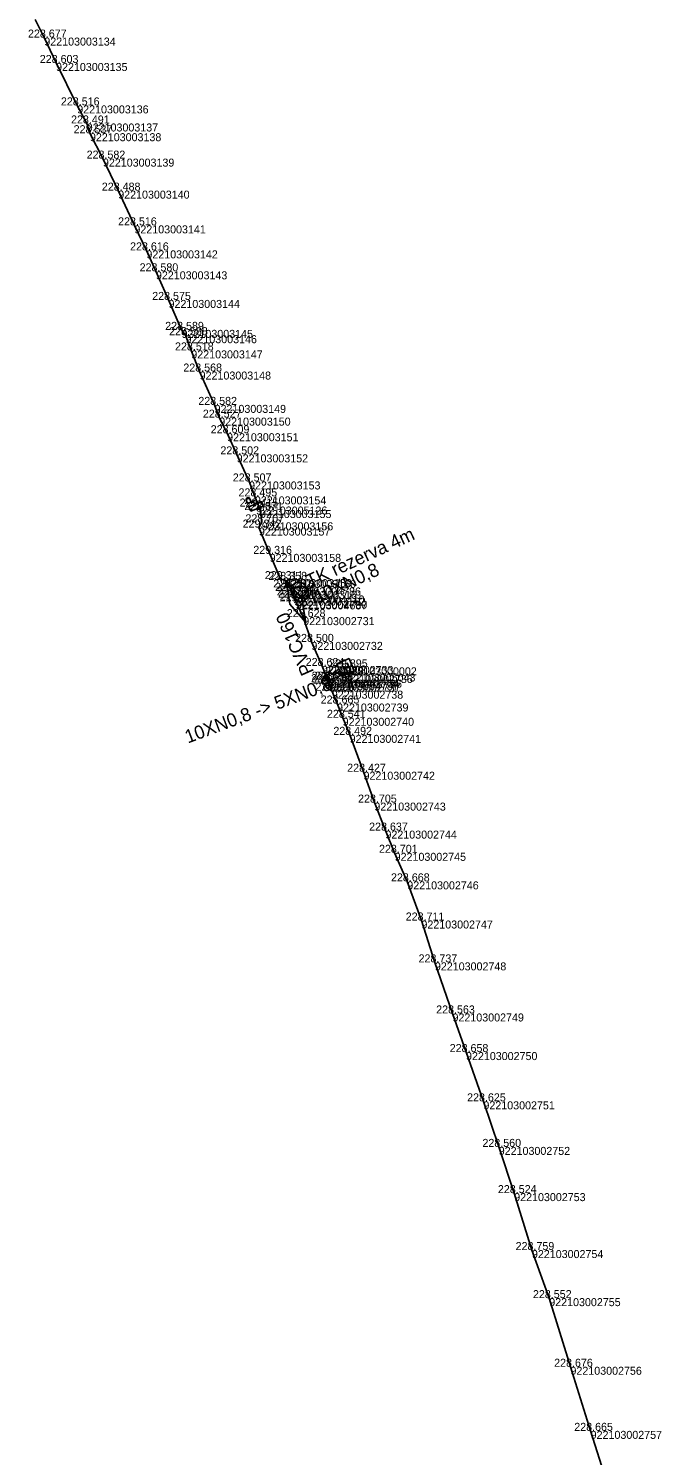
# Model space of a CAD drawing. Extents: x -771047 to -756200, y -1053876 to -1046520.
# Drawn here: x -769185.7 to -769090.7, y -1051176.3 to -1050962.3 of the extents above; entities that cross this region are included whole.
import ezdxf

# ---------------------------------------------------------------- set-up
doc = ezdxf.new("R2010")
doc.units = 0
for name, color, linetype in [('Vrstva 32', 7, 'Continuous'), ('Vrstva 33', 7, 'Continuous'), ('Vrstva 60', 7, 'Continuous'), ('Vrstva 61', 7, 'Continuous')]:
    doc.layers.add(name, color=color, linetype=linetype)

msp = doc.modelspace()

# ---------------------------------------------------------------- linework, layer by layer
at = {"layer": 'Vrstva 32'}
for p, q in [((-769141.25, -1051059.5), (-769141.73, -1051060.08)), ((-769141.73, -1051060.08), (-769140.81, -1051061.33)), ((-769141.69, -1051060.13), (-769140.21, -1051059.99)), ((-769141.42, -1051059.7), (-769140.92, -1051059.65)), ((-769141.41, -1051060.51), (-769140.02, -1051060.37)), ((-769139.85, -1051060.16), (-769141.25, -1051059.5)), ((-769141.14, -1051060.88), (-769140.38, -1051060.81)), ((-769140.81, -1051061.33), (-769139.85, -1051060.16)), ((-769140.86, -1051061.26), (-769140.75, -1051061.25))]:
    msp.add_line(p, q, dxfattribs=at)
for points in [[(-769184.68, -1050960.95), (-769183.32, -1050963.66), (-769181.55, -1050967.47), (-769178.38, -1050973.83), (-769176.95, -1050976.54), (-769176.47, -1050978), (-769174.52, -1050981.81), (-769172.23, -1050986.61), (-769169.8, -1050991.82), (-769168, -1050995.57), (-769166.57, -1050998.71), (-769164.68, -1051003), (-769162.72, -1051007.49), (-769162.13, -1051008.29), (-769161.26, -1051010.57), (-769160.01, -1051013.74), (-769157.76, -1051018.74), (-769157.07, -1051020.65), (-769155.89, -1051022.99), (-769154.45, -1051026.16), (-769152.59, -1051030.22), (-769151.72, -1051032.46), (-769150.95, -1051034.51), (-769150.68, -1051036.35), (-769151.11, -1051037.14), (-769149.5, -1051041.08), (-769147.88, -1051044.87), (-769147.24, -1051044.98), (-769146.52, -1051046.12), (-769146.24, -1051046.63), (-769145.98, -1051047.32), (-769145.81, -1051047.64)], [(-769147.03, -1051045.04), (-769144.66, -1051047.79), (-769144.1, -1051051.39), (-769146.47, -1051048.63), (-769147.03, -1051045.04)], [(-769145.81, -1051047.64), (-769145.58, -1051048.1), (-769145.57, -1051048.21), (-769144.47, -1051050.57), (-769143.24, -1051054.28), (-769141.65, -1051057.9), (-769140.76, -1051059.95), (-769140.85, -1051060.32), (-769140.58, -1051060.54)], [(-769140.36, -1051059.95), (-769138.75, -1051059.25), (-769138.35, -1051059.02), (-769138.14, -1051058.1)], [(-769140.76, -1051059.95), (-769140.36, -1051059.95), (-769140.58, -1051060.54)], [(-769140.76, -1051059.95), (-769140.36, -1051059.95), (-769140.58, -1051060.54), (-769140.18, -1051061.6)], [(-769098.99, -1051179.97), (-769101.34, -1051172.59), (-769104.37, -1051162.98), (-769107.55, -1051152.69), (-769110.15, -1051145.48), (-769112.81, -1051136.94), (-769115.13, -1051130.01), (-769117.43, -1051123.18), (-769120.04, -1051115.79), (-769122.07, -1051110), (-769124.71, -1051102.34), (-769126.73, -1051096.06), (-769128.85, -1051090.19), (-769130.75, -1051085.91), (-769132.13, -1051082.58), (-769133.79, -1051078.38), (-769135.42, -1051073.75), (-769137.5, -1051068.22), (-769138.55, -1051065.66), (-769139.39, -1051063.52), (-769140.18, -1051061.6)]]:
    msp.add_lwpolyline(points, dxfattribs=at)
for centre in [(-769145.15, -1051046.49), (-769144.84, -1051047.05)]:
    msp.add_circle(centre, 1.17, dxfattribs=at)
at = {"layer": 'Vrstva 33'}
for p, q in [((-769137.68, -1051057.9), (-769138.6, -1051058.29)), ((-769137.87, -1051057.44), (-769137.49, -1051058.37))]:
    msp.add_line(p, q, dxfattribs=at)
for points in [[(-769153.03, -1051033.05), (-769153.04, -1051032.88), (-769152.89, -1051032.7), (-769152.79, -1051032.66), (-769152.56, -1051032.69), (-769152.46, -1051032.82)], [(-769152.83, -1051033.53), (-769153.03, -1051033.05)], [(-769151.67, -1051033.06), (-769152.83, -1051033.53)], [(-769152.46, -1051032.82), (-769152.26, -1051033.3)], [(-769144.47, -1051050.57), (-769143.24, -1051054.28), (-769141.65, -1051057.9)], [(-769137.6, -1051056.79), (-769136.83, -1051058.64), (-769138.68, -1051059.4), (-769139.45, -1051057.55), (-769137.6, -1051056.79)]]:
    msp.add_lwpolyline(points, dxfattribs=at)
msp.add_lwpolyline([(-769152.35, -1051034.7), (-769152.63, -1051034.01), (-769150.76, -1051033.25), (-769150.48, -1051033.94)], close=True, dxfattribs=at)
at = {"layer": 'Vrstva 60'}
for p, q in [((-769183.32, -1050963.66), (-769183.32, -1050963.66)), ((-769181.55, -1050967.47), (-769181.55, -1050967.47)), ((-769178.38, -1050973.83), (-769178.38, -1050973.83)), ((-769176.95, -1050976.54), (-769176.95, -1050976.54)), ((-769176.47, -1050978), (-769176.47, -1050978)), ((-769174.52, -1050981.81), (-769174.52, -1050981.81)), ((-769172.23, -1050986.61), (-769172.23, -1050986.61)), ((-769169.8, -1050991.82), (-769169.8, -1050991.82)), ((-769168, -1050995.57), (-769168, -1050995.57)), ((-769166.57, -1050998.71), (-769166.57, -1050998.71)), ((-769164.68, -1051003), (-769164.68, -1051003)), ((-769162.72, -1051007.49), (-769162.72, -1051007.49)), ((-769162.13, -1051008.29), (-769162.13, -1051008.29)), ((-769161.26, -1051010.57), (-769161.26, -1051010.57)), ((-769160.01, -1051013.74), (-769160.01, -1051013.74)), ((-769157.76, -1051018.74), (-769157.76, -1051018.74)), ((-769157.07, -1051020.65), (-769157.07, -1051020.65)), ((-769155.89, -1051022.99), (-769155.89, -1051022.99)), ((-769154.45, -1051026.16), (-769154.45, -1051026.16)), ((-769152.59, -1051030.22), (-769152.59, -1051030.22)), ((-769151.72, -1051032.46), (-769151.72, -1051032.46)), ((-769151.56, -1051033.98), (-769151.56, -1051033.98)), ((-769150.95, -1051034.51), (-769150.95, -1051034.51)), ((-769151.11, -1051037.14), (-769151.11, -1051037.14)), ((-769150.68, -1051036.35), (-769150.68, -1051036.35)), ((-769149.5, -1051041.08), (-769149.5, -1051041.08)), ((-769147.88, -1051044.87), (-769147.88, -1051044.87)), ((-769147.24, -1051044.98), (-769147.24, -1051044.98)), ((-769146.52, -1051046.12), (-769146.52, -1051046.12)), ((-769146.24, -1051046.63), (-769146.24, -1051046.63)), ((-769145.98, -1051047.32), (-769145.98, -1051047.32)), ((-769145.81, -1051047.64), (-769145.81, -1051047.64)), ((-769145.58, -1051048.1), (-769145.58, -1051048.1)), ((-769145.57, -1051048.21), (-769145.57, -1051048.21)), ((-769144.47, -1051050.57), (-769144.47, -1051050.57)), ((-769143.24, -1051054.28), (-769143.24, -1051054.28)), ((-769141.65, -1051057.9), (-769141.65, -1051057.9)), ((-769138.14, -1051058.1), (-769138.14, -1051058.1)), ((-769140.85, -1051060.32), (-769140.85, -1051060.32)), ((-769140.76, -1051059.95), (-769140.76, -1051059.95)), ((-769140.58, -1051060.54), (-769140.58, -1051060.54)), ((-769140.36, -1051059.95), (-769140.36, -1051059.95)), ((-769138.75, -1051059.25), (-769138.75, -1051059.25)), ((-769138.35, -1051059.02), (-769138.35, -1051059.02)), ((-769140.18, -1051061.6), (-769140.18, -1051061.6)), ((-769139.39, -1051063.52), (-769139.39, -1051063.52)), ((-769138.55, -1051065.66), (-769138.55, -1051065.66)), ((-769137.5, -1051068.22), (-769137.5, -1051068.22)), ((-769135.42, -1051073.75), (-769135.42, -1051073.75)), ((-769133.79, -1051078.38), (-769133.79, -1051078.38)), ((-769132.13, -1051082.58), (-769132.13, -1051082.58)), ((-769130.75, -1051085.91), (-769130.75, -1051085.91)), ((-769128.85, -1051090.19), (-769128.85, -1051090.19)), ((-769126.73, -1051096.06), (-769126.73, -1051096.06)), ((-769124.71, -1051102.34), (-769124.71, -1051102.34)), ((-769122.07, -1051110), (-769122.07, -1051110)), ((-769120.04, -1051115.79), (-769120.04, -1051115.79)), ((-769117.43, -1051123.18), (-769117.43, -1051123.18)), ((-769115.13, -1051130.01), (-769115.13, -1051130.01)), ((-769112.81, -1051136.94), (-769112.81, -1051136.94)), ((-769110.15, -1051145.48), (-769110.15, -1051145.48)), ((-769107.55, -1051152.69), (-769107.55, -1051152.69)), ((-769104.37, -1051162.98), (-769104.37, -1051162.98)), ((-769101.34, -1051172.59), (-769101.34, -1051172.59))]:
    msp.add_line(p, q, dxfattribs=at)

# ---------------------------------------------------------------- texts
at = {"layer": 'Vrstva 32'}
for s, rotation, p in [('TK rezerva 4m', 24.8257, (-769143.47, -1051046.2)), ('10XN0,8', 24.812, (-769142.3, -1051048.53)), ('10XN0,8 -> 5XN0,8', 20.611, (-769161.78, -1051069.53))]:
    msp.add_text(s, height=2, rotation=rotation, dxfattribs=at).set_placement(p)
at = {"layer": 'Vrstva 33'}
msp.add_text('PVC160', height=2, rotation=113.7198, dxfattribs=at).set_placement((-769142.82, -1051058.77))
at = {"layer": 'Vrstva 60'}
for s, p in [('922103003134', (-769183.32, -1050964.86)), ('922103003135', (-769181.55, -1050968.67)), ('922103003136', (-769178.38, -1050975.03)), ('922103003137', (-769176.95, -1050977.74)), ('922103003138', (-769176.47, -1050979.2)), ('922103003139', (-769174.52, -1050983.01)), ('922103003140', (-769172.23, -1050987.81)), ('922103003141', (-769169.8, -1050993.02)), ('922103003142', (-769168, -1050996.77)), ('922103003143', (-769166.57, -1050999.91)), ('922103003144', (-769164.68, -1051004.2)), ('922103003145', (-769162.72, -1051008.69)), ('922103003146', (-769162.13, -1051009.49)), ('922103003147', (-769161.26, -1051011.77)), ('922103003148', (-769160.01, -1051014.94)), ('922103003149', (-769157.76, -1051019.94)), ('922103003150', (-769157.07, -1051021.85)), ('922103003151', (-769155.89, -1051024.19)), ('922103003152', (-769154.45, -1051027.36)), ('922103003153', (-769152.59, -1051031.42)), ('922103003154', (-769151.72, -1051033.66)), ('922103005126', (-769151.56, -1051035.18)), ('922103003155', (-769150.95, -1051035.71)), ('922103003157', (-769151.11, -1051038.34)), ('922103003156', (-769150.68, -1051037.55)), ('922103003158', (-769149.5, -1051042.28)), ('922103003159', (-769147.88, -1051046.07)), ('922103003160', (-769147.24, -1051046.18)), ('922103004786', (-769146.52, -1051047.32)), ('922103003161', (-769146.24, -1051047.83)), ('922103004410', (-769145.98, -1051048.52)), ('922103003162', (-769145.81, -1051048.84)), ('922103002730', (-769145.58, -1051049.3)), ('922103004687', (-769145.57, -1051049.41)), ('922103002731', (-769144.47, -1051051.77)), ('922103002732', (-769143.24, -1051055.48)), ('922103002733', (-769141.65, -1051059.1)), ('922103000002', (-769138.14, -1051059.3)), ('922103004787', (-769140.85, -1051061.52)), ('922103002734', (-769140.76, -1051061.15)), ('922103002737', (-769140.58, -1051061.74)), ('922103002735', (-769140.36, -1051061.15)), ('922103002736', (-769138.75, -1051060.45)), ('922103005043', (-769138.35, -1051060.22)), ('922103002738', (-769140.18, -1051062.8)), ('922103002739', (-769139.39, -1051064.72)), ('922103002740', (-769138.55, -1051066.86)), ('922103002741', (-769137.5, -1051069.42)), ('922103002742', (-769135.42, -1051074.95)), ('922103002743', (-769133.79, -1051079.58)), ('922103002744', (-769132.13, -1051083.78)), ('922103002745', (-769130.75, -1051087.11)), ('922103002746', (-769128.85, -1051091.39)), ('922103002747', (-769126.73, -1051097.26)), ('922103002748', (-769124.71, -1051103.54)), ('922103002749', (-769122.07, -1051111.2)), ('922103002750', (-769120.04, -1051116.99)), ('922103002751', (-769117.43, -1051124.38)), ('922103002752', (-769115.13, -1051131.21)), ('922103002753', (-769112.81, -1051138.14)), ('922103002754', (-769110.15, -1051146.68)), ('922103002755', (-769107.55, -1051153.89)), ('922103002756', (-769104.37, -1051164.18)), ('922103002757', (-769101.34, -1051173.79))]:
    msp.add_text(s, height=1.2, dxfattribs=at).set_placement(p)
at = {"layer": 'Vrstva 61'}
for s, p in [('228.677', (-769185.77, -1050963.66)), ('228.603', (-769184, -1050967.47)), ('228.516', (-769180.83, -1050973.83)), ('228.491', (-769179.31, -1050976.54)), ('228.537', (-769178.92, -1050978)), ('228.582', (-769176.97, -1050981.81)), ('228.488', (-769174.69, -1050986.61)), ('228.516', (-769172.25, -1050991.82)), ('228.616', (-769170.45, -1050995.57)), ('228.580', (-769169.02, -1050998.71)), ('228.575', (-769167.13, -1051003)), ('228.589', (-769165.18, -1051007.49)), ('228.588', (-769164.59, -1051008.29)), ('228.518', (-769163.71, -1051010.57)), ('228.568', (-769162.46, -1051013.74)), ('228.582', (-769160.21, -1051018.74)), ('228.527', (-769159.53, -1051020.65)), ('228.609', (-769158.35, -1051022.99)), ('228.502', (-769156.9, -1051026.16)), ('228.507', (-769155.04, -1051030.22)), ('228.495', (-769154.18, -1051032.46)), ('229.415', (-769154.01, -1051033.98)), ('228.571', (-769153.31, -1051034.51)), ('228.707', (-769153.14, -1051036.35)), ('229.342', (-769153.56, -1051037.14)), ('229.316', (-769151.96, -1051041.08)), ('229.311', (-769150.24, -1051044.87)), ('228.358', (-769149.7, -1051044.98)), ('228.262', (-769148.97, -1051046.12)), ('228.318', (-769148.69, -1051046.63)), ('228.605', (-769148.43, -1051047.32)), ('228.446', (-769148.26, -1051047.64)), ('228.470', (-769148.03, -1051048.1)), ('228.579', (-769148.02, -1051048.21)), ('228.628', (-769146.93, -1051050.57)), ('228.500', (-769145.69, -1051054.28)), ('228.624', (-769144.1, -1051057.9)), ('228.659', (-769143.21, -1051059.95)), ('228.741', (-769142.71, -1051059.95)), ('228.823', (-769141.2, -1051059.25)), ('229.002', (-769140.8, -1051059.02)), ('229.895', (-769140.6, -1051058.1)), ('228.879', (-769143.3, -1051060.32)), ('228.716', (-769143.03, -1051060.54)), ('228.806', (-769142.63, -1051061.6)), ('228.665', (-769141.85, -1051063.52)), ('228.541', (-769140.91, -1051065.66)), ('228.492', (-769139.95, -1051068.22)), ('228.427', (-769137.87, -1051073.75)), ('228.705', (-769136.24, -1051078.38)), ('228.637', (-769134.58, -1051082.58)), ('228.701', (-769133.1, -1051085.91)), ('228.668', (-769131.3, -1051090.19)), ('228.711', (-769129.09, -1051096.06)), ('228.737', (-769127.16, -1051102.34)), ('228.563', (-769124.52, -1051110)), ('228.658', (-769122.49, -1051115.79)), ('228.625', (-769119.88, -1051123.18)), ('228.560', (-769117.58, -1051130.01)), ('228.524', (-769115.26, -1051136.94)), ('228.759', (-769112.6, -1051145.48)), ('228.552', (-769110, -1051152.69)), ('228.676', (-769106.82, -1051162.98)), ('228.665', (-769103.8, -1051172.59))]:
    msp.add_text(s, height=1.2, dxfattribs=at).set_placement(p)

doc.saveas('drawing.dxf')
